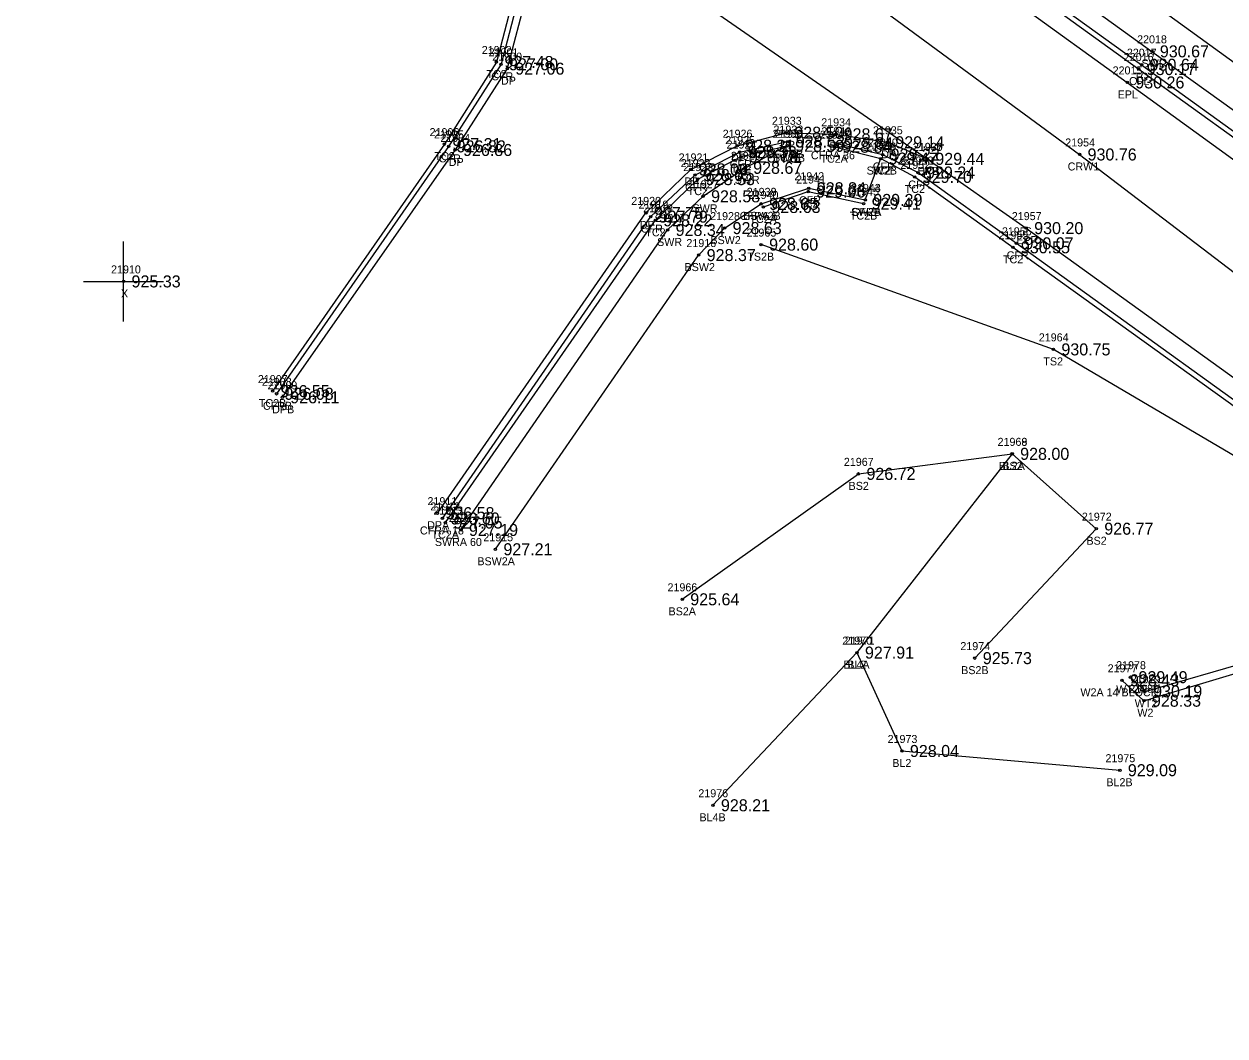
# Model space of a CAD drawing. Extents: x 1576181 to 1577685, y 1099396 to 1101490.
# Drawn here: x 1577294.3 to 1577444.3, y 1100809.1 to 1100935.6 of the extents above; entities that cross this region are included whole.
import ezdxf

# ---------------------------------------------------------------- set-up
doc = ezdxf.new("R2010")
doc.units = 0
for name, color, linetype in [('RD_DTM_BkLn1', 7, 'Continuous'), ('RD_DTM_BkLn2', 7, 'Continuous'), ('RD_DTM_BkLn_txCode', 7, 'Continuous'), ('RD_EX_BldgApp', 7, 'Continuous'), ('RD_EX_Conc', 7, 'Continuous'), ('RD_EX_Conc_txCode', 7, 'Continuous'), ('RD_EX_Driveway', 7, 'Continuous'), ('RD_EX_Driveway_txCode', 7, 'Continuous'), ('RD_EX_Misc', 7, 'Continuous'), ('RD_EX_Misc_txCode', 7, 'Continuous'), ('RD_EX_Road', 7, 'Continuous'), ('RD_EX_Road_txCode', 7, 'Continuous'), ('RD_EX_TX_Conc_ELEV', 7, 'Continuous'), ('RD_EX_TX_Driveway_ELEV', 7, 'Continuous'), ('RD_EX_TX_Misc_ELEV', 7, 'Continuous'), ('RD_EX_TX_Road_ELEV', 7, 'Continuous'), ('RD_HC_Survey_ELEV', 7, 'Continuous'), ('RD_HC_Survey_txCode', 7, 'Continuous'), ('RD_SMD_Locator', 7, 'Continuous')]:
    doc.layers.add(name, color=color, linetype=linetype)

msp = doc.modelspace()

# ---------------------------------------------------------------- linework, layer by layer
at = {"layer": 'RD_DTM_BkLn1'}
msp.add_line((1577398.36, 1100857.03), (1577380.37, 1100837.96), dxfattribs=at)
for points in [[(1577238.59, 1101054.64), (1577263.64, 1101036.24), (1577303.95, 1101006.72), (1577344.58, 1100977.95), (1577386.9, 1100948.15), (1577426.17, 1100919.26), (1577465.69, 1100889.09), (1577507.94, 1100862.82), (1577553.41, 1100842.12), (1577599.84, 1100824.14), (1577646.74, 1100805.8)], [(1577417.75, 1100881.86), (1577398.36, 1100857.03), (1577403.98, 1100844.74), (1577431.2, 1100842.34)]]:
    msp.add_lwpolyline(points, dxfattribs=at)
at = {"layer": 'RD_DTM_BkLn2'}
for points in [[(1577260.56, 1101056.27), (1577271.65, 1101048), (1577312.74, 1101017.67), (1577352.97, 1100988.91), (1577392.63, 1100960.2), (1577433.92, 1100930.47), (1577452.73, 1100916.9), (1577458.15, 1100912.82)], [(1577354.73, 1100945.19), (1577355.6, 1100939.46), (1577353.33, 1100930.81), (1577346.83, 1100920.55), (1577325.37, 1100889.7)], [(1577346.96, 1100873.28), (1577373.17, 1100911.03), (1577378.47, 1100916.18), (1577383.88, 1100919), (1577389.65, 1100920.34)], [(1577395.54, 1100920.23), (1577401.33, 1100918.75), (1577405.58, 1100916.45), (1577417.84, 1100907.66), (1577459.24, 1100877.93), (1577501.01, 1100850.46), (1577548.36, 1100828.61), (1577593.56, 1100811.04), (1577656.23, 1100786.49)], [(1577386.68, 1100912.7), (1577392.28, 1100914.63), (1577399.2, 1100913.12)], [(1577458.77, 1100859.82), (1577450.85, 1100878.45), (1577422.9, 1100894.91), (1577386.39, 1100908)], [(1577376.54, 1100863.69), (1577398.55, 1100879.36), (1577417.75, 1100881.86), (1577428.26, 1100872.51), (1577413.08, 1100856.34)], [(1577432.53, 1100853.96), (1577434.36, 1100852.19), (1577447.88, 1100856.09), (1577457.13, 1100856.82), (1577470.14, 1100851.87), (1577480.17, 1100839.59), (1577486.13, 1100817.13), (1577494.64, 1100804.62), (1577509.91, 1100799.91), (1577531.35, 1100805.03), (1577541.32, 1100806.67), (1577560.38, 1100798.33), (1577576.37, 1100784.65), (1577583.76, 1100755.46)]]:
    msp.add_lwpolyline(points, dxfattribs=at)
at = {"layer": 'RD_EX_BldgApp'}
msp.add_lwpolyline([(1577431.47, 1100853.57), (1577434.21, 1100851.02), (1577448.25, 1100855.22), (1577457, 1100855.58), (1577470.32, 1100850.24), (1577479.05, 1100838.66), (1577484.72, 1100816.57), (1577493.67, 1100803.21), (1577510, 1100798.11), (1577531.96, 1100803.27), (1577542, 1100804.92), (1577559.8, 1100797.02), (1577574.7, 1100783.55), (1577581.82, 1100754.82)], dxfattribs=at)
at = {"layer": 'RD_EX_Conc'}
msp.add_line((1577399.41, 1100913.58), (1577401.33, 1100918.75), dxfattribs=at)
for points in [[(1577260.09, 1101055.74), (1577271.3, 1101047.57), (1577312.39, 1101017.33), (1577352.65, 1100988.38), (1577392.28, 1100959.71), (1577433.56, 1100929.93), (1577452.44, 1100916.35), (1577457.82, 1100912.39)], [(1577352.79, 1100991.57), (1577355.36, 1100995.86), (1577382.69, 1100975.99), (1577386.31, 1100973.35), (1577395.61, 1100966.73), (1577398.83, 1100964.39), (1577422.4, 1100947.35), (1577425.71, 1100945.1), (1577453.6, 1100924.89), (1577456.82, 1100922.74)], [(1577352.79, 1100991.57), (1577393.94, 1100961.92), (1577435.2, 1100932.14), (1577453.92, 1100918.67), (1577452.73, 1100916.9)], [(1577355.23, 1100945.27), (1577356.21, 1100939.37), (1577353.9, 1100930.52), (1577347.36, 1100920.27), (1577325.86, 1100889.36)], [(1577346.59, 1100873.79), (1577372.6, 1100911.49), (1577378.13, 1100916.68), (1577383.71, 1100919.55), (1577389.73, 1100920.87)], [(1577395.74, 1100920.66), (1577401.57, 1100919.25), (1577405.99, 1100917), (1577418.29, 1100908.16), (1577459.56, 1100878.43), (1577501.42, 1100850.96), (1577548.66, 1100829.07), (1577593.79, 1100811.49), (1577656.52, 1100787)], [(1577348.89, 1100872.35), (1577374.71, 1100909.83), (1577379.14, 1100914.03), (1577384.4, 1100917.59), (1577389.65, 1100920.34)], [(1577386.39, 1100913.09), (1577392.35, 1100915.04), (1577399.41, 1100913.58)], [(1577353.2, 1100869.94), (1577378.59, 1100906.69), (1577381.83, 1100910.06), (1577386.39, 1100913.09)]]:
    msp.add_lwpolyline(points, dxfattribs=at)
at = {"layer": 'RD_EX_Driveway'}
for points in [[(1577345.18, 1100963.67), (1577351.94, 1100956.5), (1577354.99, 1100950.41), (1577356.23, 1100945.68), (1577357.12, 1100939.35), (1577354.68, 1100929.98), (1577348.16, 1100919.82), (1577326.57, 1100888.92)], [(1577345.95, 1100874.45), (1577372.01, 1100911.96), (1577377.6, 1100917.39), (1577383.41, 1100920.35), (1577389.54, 1100921.97), (1577395.7, 1100921.78), (1577402.16, 1100920.78), (1577407.15, 1100918.71)]]:
    msp.add_lwpolyline(points, dxfattribs=at)
at = {"layer": 'RD_EX_Misc'}
for p, q in [((1577306.75, 1100898.4), (1577306.75, 1100908.4)), ((1577301.75, 1100903.4), (1577311.75, 1100903.4))]:
    msp.add_line(p, q, dxfattribs=at)
at = {"layer": 'RD_EX_Road'}
for points in [[(1577251.26, 1101061.34), (1577255.44, 1101056.29), (1577270.08, 1101045.56), (1577310.68, 1101015.78), (1577351.28, 1100986.44), (1577391.25, 1100957.77), (1577432.13, 1100928.26), (1577451.03, 1100914.55), (1577473.4, 1100898.43), (1577474.18, 1100899.6), (1577481.34, 1100895.67), (1577490.14, 1100894.7), (1577498.51, 1100899.09), (1577503.3, 1100907.84), (1577513.46, 1100934.77)], [(1577078.76, 1100718.33), (1577101.64, 1100758.92), (1577113.34, 1100780.09), (1577125.29, 1100804.69), (1577146.47, 1100851.25), (1577166.06, 1100897.32), (1577205.17, 1100988.68), (1577222.29, 1101028.96), (1577224.55, 1101032.02), (1577228.3, 1101034.47), (1577233.18, 1101036.1), (1577233.18, 1101036.1), (1577237.42, 1101035.84), (1577245.43, 1101032.85), (1577248.28, 1101031.55), (1577256.85, 1101026.16), (1577298.2, 1100997.6), (1577319.21, 1100982.29), (1577334.07, 1100971.38), (1577345.18, 1100963.67), (1577378, 1100938.95), (1577407.15, 1100918.71), (1577419.5, 1100910.06), (1577460.72, 1100880.37)]]:
    msp.add_lwpolyline(points, dxfattribs=at)
at = {"layer": 'RD_SMD_Locator'}
for centre in [(1577435.2, 1100932.14), (1577353.33, 1100930.81), (1577353.9, 1100930.52), (1577354.68, 1100929.98), (1577433.56, 1100929.93), (1577433.92, 1100930.47), (1577432.13, 1100928.26), (1577389.54, 1100921.97), (1577346.83, 1100920.55), (1577389.73, 1100920.87), (1577395.7, 1100921.78), (1577395.74, 1100920.66), (1577402.16, 1100920.78), (1577347.36, 1100920.27), (1577348.16, 1100919.82), (1577383.41, 1100920.35), (1577383.71, 1100919.55), (1577383.88, 1100919), (1577389.65, 1100920.34), (1577389.65, 1100920.34), (1577395.54, 1100920.23), (1577401.57, 1100919.25), (1577426.17, 1100919.26), (1577384.4, 1100917.59), (1577401.33, 1100918.75), (1577401.33, 1100918.75), (1577407.15, 1100918.71), (1577407.15, 1100918.71), (1577377.6, 1100917.39), (1577378.13, 1100916.68), (1577378.47, 1100916.18), (1577405.58, 1100916.45), (1577405.99, 1100917), (1577392.28, 1100914.63), (1577392.35, 1100915.04), (1577379.14, 1100914.03), (1577386.39, 1100913.09), (1577386.39, 1100913.09), (1577399.2, 1100913.12), (1577399.41, 1100913.58), (1577399.41, 1100913.58), (1577372.01, 1100911.96), (1577372.6, 1100911.49), (1577386.68, 1100912.7), (1577373.17, 1100911.03), (1577381.83, 1100910.06), (1577419.5, 1100910.06), (1577374.71, 1100909.83), (1577386.39, 1100908), (1577417.84, 1100907.66), (1577418.29, 1100908.16), (1577378.59, 1100906.69), (1577306.75, 1100903.4), (1577422.9, 1100894.91), (1577325.37, 1100889.7), (1577325.86, 1100889.36), (1577326.57, 1100888.92), (1577417.75, 1100881.86), (1577417.75, 1100881.86), (1577398.55, 1100879.36), (1577345.95, 1100874.45), (1577346.59, 1100873.79), (1577346.96, 1100873.28), (1577428.26, 1100872.51), (1577348.89, 1100872.35), (1577353.2, 1100869.94), (1577376.54, 1100863.69), (1577398.36, 1100857.03), (1577398.36, 1100857.03), (1577413.08, 1100856.34), (1577431.47, 1100853.57), (1577432.53, 1100853.96), (1577434.36, 1100852.19), (1577434.21, 1100851.02), (1577403.98, 1100844.74), (1577431.2, 1100842.34), (1577380.37, 1100837.96)]:
    msp.add_circle(centre, 0.15, dxfattribs=at)

# ---------------------------------------------------------------- texts
at = {"layer": 'RD_DTM_BkLn_txCode'}
for s, p in [('21965', (1577384.57, 1100909)), ('TS2B', (1577384.67, 1100906)), ('21964', (1577421.08, 1100895.91)), ('TS2', (1577421.65, 1100892.91)), ('21968', (1577415.93, 1100882.86)), ('21969', (1577415.93, 1100882.86)), ('21967', (1577396.73, 1100880.36)), ('BL2A', (1577416.06, 1100879.86)), ('BS2', (1577416.52, 1100879.86)), ('BS2', (1577397.32, 1100877.36)), ('21972', (1577426.46, 1100873.51)), ('BS2', (1577427.03, 1100870.51)), ('21966', (1577374.7, 1100864.69)), ('BS2A', (1577374.83, 1100861.69)), ('21970', (1577396.53, 1100858.03)), ('21971', (1577396.85, 1100858.03)), ('21974', (1577411.28, 1100857.34)), ('BL4A', (1577396.67, 1100855.03)), ('BL2', (1577397.16, 1100855.03)), ('BS2B', (1577411.38, 1100854.34)), ('21973', (1577402.19, 1100845.74)), ('21975', (1577429.41, 1100843.34)), ('BL2', (1577402.78, 1100842.74)), ('BL2B', (1577429.52, 1100840.34)), ('21976', (1577378.55, 1100838.96)), ('BL4B', (1577378.69, 1100835.96))]:
    msp.add_text(s, height=1, dxfattribs=at).set_placement(p)
at = {"layer": 'RD_EX_Conc_txCode'}
for s, p in [('22018', (1577433.36, 1100933.14)), ('21902', (1577351.5, 1100931.81)), ('21901', (1577352.35, 1100931.52)), ('22016', (1577431.7, 1100930.93)), ('22017', (1577432.08, 1100931.47)), ('SWL', (1577433.91, 1100930.14)), ('TC2', (1577352.09, 1100928.81)), ('CFR', (1577352.68, 1100928.52)), ('CFL', (1577432.35, 1100927.93)), ('TC1', (1577432.96, 1100928.47)), ('21906', (1577344.98, 1100921.55)), ('21905', (1577345.53, 1100921.27)), ('21930', (1577387.82, 1100921.34)), ('21932', (1577387.94, 1100921.87)), ('21931', (1577388.14, 1100921.34)), ('21947', (1577393.74, 1100921.23)), ('21946', (1577393.92, 1100921.66)), ('21925', (1577381.91, 1100920.55)), ('21924', (1577382.08, 1100920)), ('21948', (1577399.54, 1100919.75)), ('21949', (1577399.54, 1100919.75)), ('21950', (1577399.74, 1100920.25)), ('TC2', (1577345.59, 1100918.55)), ('CFR', (1577346.13, 1100918.27)), ('21929', (1577382.61, 1100918.59)), ('SWRB', (1577387.87, 1100918.34)), ('TC2B', (1577387.94, 1100918.34)), ('CFRB', (1577388.03, 1100918.87)), ('CFRA 36', (1577392.61, 1100918.66)), ('TC2A', (1577393.8, 1100918.23)), ('21922', (1577376.34, 1100917.68)), ('21923', (1577376.67, 1100917.18)), ('CFR', (1577382.48, 1100917.55)), ('TC2', (1577382.63, 1100917)), ('SW2B', (1577399.57, 1100916.75)), ('TC2', (1577400.09, 1100916.75)), ('CFR', (1577400.34, 1100917.25)), ('21952', (1577403.78, 1100917.45)), ('21953', (1577404.2, 1100918)), ('SWR', (1577383.09, 1100915.59)), ('21942', (1577390.55, 1100916.04)), ('21941', (1577390.76, 1100915.63)), ('CFR', (1577376.9, 1100914.68)), ('TC2', (1577377.22, 1100914.18)), ('21927', (1577377.35, 1100915.03)), ('21938', (1577384.6, 1100914.09)), ('21939', (1577384.6, 1100914.09)), ('21940', (1577384.84, 1100913.7)), ('21945', (1577397.4, 1100914.12)), ('21943', (1577397.62, 1100914.58)), ('21944', (1577397.62, 1100914.58)), ('TC2', (1577404.33, 1100914.45)), ('CFR', (1577404.77, 1100915)), ('21919', (1577371.08, 1100912.49)), ('TC2', (1577391.03, 1100912.63)), ('CFR', (1577391.12, 1100913.04)), ('21918', (1577371.66, 1100912.03)), ('21917', (1577373.2, 1100910.83)), ('SWR', (1577377.83, 1100912.03)), ('21928', (1577380.03, 1100911.06)), ('CFRA 6', (1577383.72, 1100911.09)), ('BSW2B', (1577384.16, 1100911.09)), ('TC2A', (1577384.94, 1100910.7)), ('TC2B', (1577397.48, 1100911.12)), ('SW2A', (1577397.63, 1100911.58)), ('CFRB', (1577397.71, 1100911.58)), ('CFR', (1577371.37, 1100909.49)), ('21956', (1577416.47, 1100909.16)), ('TC2', (1577371.93, 1100909.03)), ('SWR', (1577373.4, 1100907.83)), ('21916', (1577377.06, 1100907.69)), ('BSW2', (1577380.06, 1100908.06)), ('21955', (1577416.04, 1100908.66)), ('CFR', (1577417.06, 1100906.16)), ('BSW2', (1577376.83, 1100904.69)), ('TC2', (1577416.6, 1100905.66)), ('21907', (1577323.53, 1100890.7)), ('21908', (1577324.03, 1100890.36)), ('TC2B', (1577323.65, 1100887.7)), ('CFRB', (1577324.16, 1100887.36)), ('21912', (1577345.07, 1100874.79)), ('21913', (1577345.45, 1100874.28)), ('21914', (1577347.38, 1100873.35)), ('CFRA 18', (1577343.77, 1100871.79)), ('TC2A', (1577345.23, 1100871.28)), ('SWRA 60', (1577345.64, 1100870.35)), ('21915', (1577351.69, 1100870.94)), ('BSW2A', (1577350.95, 1100867.94))]:
    msp.add_text(s, height=1, dxfattribs=at).set_placement(p)
at = {"layer": 'RD_EX_Driveway_txCode'}
for s, p in [('21900', (1577352.81, 1100930.98)), ('DP', (1577353.9, 1100927.98)), ('21933', (1577387.74, 1100922.97)), ('21934', (1577393.9, 1100922.78)), ('21926', (1577381.59, 1100921.35)), ('21935', (1577400.36, 1100921.78)), ('21904', (1577346.33, 1100920.82)), ('DP', (1577388.76, 1100919.97)), ('DP', (1577394.92, 1100919.78)), ('21936', (1577405.33, 1100919.71)), ('21921', (1577376.09, 1100918.39)), ('DP', (1577382.63, 1100918.35)), ('DP', (1577401.38, 1100918.78)), ('DP', (1577347.38, 1100917.82)), ('DPB', (1577405.9, 1100916.71)), ('DP', (1577376.82, 1100915.39)), ('21920', (1577370.17, 1100912.96)), ('DP', (1577371.23, 1100909.96)), ('21909', (1577324.74, 1100889.92)), ('DPB', (1577325.32, 1100886.92)), ('21911', (1577344.72, 1100875.45)), ('DPA', (1577344.68, 1100872.45))]:
    msp.add_text(s, height=1, dxfattribs=at).set_placement(p)
at = {"layer": 'RD_EX_Misc_txCode'}
for s, p in [('21910', (1577305.19, 1100904.4)), ('X', (1577306.43, 1100901.4)), ('21977', (1577429.68, 1100854.57)), ('21978', (1577430.74, 1100854.96)), ('21979', (1577432.57, 1100853.19)), ('W2A 14 BLOCK', (1577426.28, 1100851.57)), ('WT2A', (1577430.74, 1100851.96)), ('21980', (1577432.38, 1100852.02)), ('WT2', (1577433.06, 1100850.19)), ('W2', (1577433.39, 1100849.02))]:
    msp.add_text(s, height=1, dxfattribs=at).set_placement(p)
at = {"layer": 'RD_EX_Road_txCode'}
for s, p in [('22015', (1577430.3, 1100929.26)), ('EPL', (1577430.93, 1100926.26)), ('21937', (1577405.36, 1100919.71)), ('EPR', (1577405.92, 1100916.71)), ('21957', (1577417.71, 1100911.06)), ('EPR', (1577418.27, 1100908.06))]:
    msp.add_text(s, height=1, dxfattribs=at).set_placement(p)
at = {"layer": 'RD_EX_TX_Conc_ELEV'}
for s, p in [('930.67', (1577436.2, 1100931.39)), ('927.48', (1577354.33, 1100930.06)), ('927.00', (1577354.9, 1100929.77)), ('930.64', (1577434.92, 1100929.72)), ('930.17', (1577434.56, 1100929.18)), ('927.31', (1577347.83, 1100919.8)), ('926.82', (1577348.36, 1100919.52)), ('928.59', (1577390.65, 1100919.59)), ('928.59', (1577390.65, 1100919.59)), ('928.52', (1577390.73, 1100920.12)), ('928.84', (1577396.54, 1100919.48)), ('928.84', (1577396.74, 1100919.91)), ('928.33', (1577384.71, 1100918.8)), ('928.78', (1577384.88, 1100918.25)), ('929.47', (1577402.33, 1100918)), ('929.47', (1577402.33, 1100918)), ('929.22', (1577402.57, 1100918.5)), ('928.67', (1577385.4, 1100916.84)), ('929.24', (1577406.99, 1100916.25)), ('928.05', (1577379.13, 1100915.93)), ('928.53', (1577379.47, 1100915.43)), ('929.70', (1577406.58, 1100915.7)), ('928.58', (1577380.14, 1100913.28)), ('929.06', (1577393.28, 1100913.88)), ('928.84', (1577393.35, 1100914.29)), ('928.65', (1577387.39, 1100912.34)), ('928.65', (1577387.39, 1100912.34)), ('928.63', (1577387.68, 1100911.95)), ('929.41', (1577400.2, 1100912.37)), ('929.39', (1577400.41, 1100912.83)), ('929.39', (1577400.41, 1100912.83)), ('927.79', (1577373.6, 1100910.74)), ('928.22', (1577374.17, 1100910.28)), ('928.34', (1577375.71, 1100909.08)), ('928.63', (1577382.83, 1100909.31)), ('930.07', (1577419.29, 1100907.41)), ('928.37', (1577379.59, 1100905.94)), ('930.55', (1577418.84, 1100906.91)), ('926.55', (1577326.37, 1100888.95)), ('926.08', (1577326.86, 1100888.61)), ('926.60', (1577347.59, 1100873.04)), ('927.05', (1577347.96, 1100872.53)), ('927.19', (1577349.89, 1100871.6)), ('927.21', (1577354.2, 1100869.19))]:
    msp.add_text(s, height=1.5, dxfattribs=at).set_placement(p)
at = {"layer": 'RD_EX_TX_Driveway_ELEV'}
for s, p in [('927.06', (1577355.68, 1100929.23)), ('928.50', (1577390.54, 1100921.22)), ('928.67', (1577396.7, 1100921.03)), ('926.86', (1577349.16, 1100919.07)), ('928.31', (1577384.41, 1100919.6)), ('929.14', (1577403.16, 1100920.03)), ('929.44', (1577408.15, 1100917.96)), ('928.06', (1577378.6, 1100916.64)), ('927.75', (1577373.01, 1100911.21)), ('926.11', (1577327.57, 1100888.17)), ('926.58', (1577346.95, 1100873.7))]:
    msp.add_text(s, height=1.5, dxfattribs=at).set_placement(p)
at = {"layer": 'RD_EX_TX_Misc_ELEV'}
for s, p in [('928.60', (1577387.39, 1100907.25)), ('925.33', (1577307.75, 1100902.65)), ('930.75', (1577423.9, 1100894.16)), ('928.00', (1577418.75, 1100881.11)), ('928.00', (1577418.75, 1100881.11)), ('926.72', (1577399.55, 1100878.61)), ('926.77', (1577429.26, 1100871.76)), ('925.64', (1577377.54, 1100862.94)), ('927.91', (1577399.36, 1100856.28)), ('927.91', (1577399.36, 1100856.28)), ('925.73', (1577414.08, 1100855.59)), ('929.49', (1577433.53, 1100853.21)), ('928.43', (1577432.47, 1100852.82)), ('928.33', (1577435.21, 1100850.27)), ('930.19', (1577435.36, 1100851.44)), ('928.04', (1577404.98, 1100843.99)), ('929.09', (1577432.2, 1100841.59)), ('928.21', (1577381.37, 1100837.21))]:
    msp.add_text(s, height=1.5, dxfattribs=at).set_placement(p)
at = {"layer": 'RD_EX_TX_Road_ELEV'}
for s, p in [('930.26', (1577433.13, 1100927.51)), ('929.44', (1577408.15, 1100917.96)), ('930.20', (1577420.5, 1100909.31))]:
    msp.add_text(s, height=1.5, dxfattribs=at).set_placement(p)
at = {"layer": 'RD_HC_Survey_ELEV'}
msp.add_text('930.76', height=1.5, dxfattribs=at).set_placement((1577427.17, 1100918.51))
at = {"layer": 'RD_HC_Survey_txCode'}
for s, p in [('21954', (1577424.38, 1100920.26)), ('CRW1', (1577424.69, 1100917.26))]:
    msp.add_text(s, height=1, dxfattribs=at).set_placement(p)

doc.saveas('drawing.dxf')
